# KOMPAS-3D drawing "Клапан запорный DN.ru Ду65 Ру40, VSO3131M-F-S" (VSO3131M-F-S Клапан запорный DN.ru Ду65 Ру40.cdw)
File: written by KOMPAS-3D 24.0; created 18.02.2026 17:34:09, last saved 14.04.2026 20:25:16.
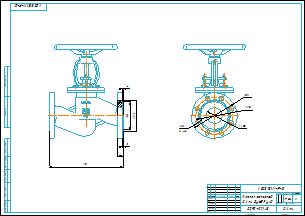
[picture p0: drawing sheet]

Document properties: Автор: R2D2; Форматы листов документа: A2; Полное имя файла: VSO3131M-F-S Клапан запорный DN.ru Ду65 Ру40.m3d; Масса: 17.64; Наименование: Клапан запорный DN.ru Ду65 Ру40; Количество листов документа: 1; Примечание: D090-02143

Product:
- Part/product: Клапан запорный DN.ru Ду65 Ру40  | designation VSO3131M-F-S
    Масса: 17.64
    Раздел спецификации: Прочие изделия
    Примечание: D090-02143

Referenced files in E:\Работа\Зайцев\Для компаса\: чертеж DN.ru А3.cdt
Referenced files in E:\Работа\Зайцев\VSO3131M-F-S Клапан запорный DN.ru Ду15-100 Ру40\DN65\: VSO3131M-F-S Клапан запорный DN.ru Ду65 Ру40.m3d
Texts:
  чертеж DN.ru А3.cdt
  Клапан запорный
  DN.ru Ду65 Ру40
  VSO3131M-F-S
  Клапан запорный DN.ru Ду65 Ру40
  VSO3131M-F-S Клапан запорный DN.ru Ду65 Ру40
Dimensions and other numbers on the sheet: 1:2; 0; 1; 2; 17,64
